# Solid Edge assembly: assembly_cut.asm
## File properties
Author: ptcarter
Template: Normal.asm
Last saved by: ptcarter
Revision: 33
Application: Solid Edge
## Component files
baseplate.psm
motormount.psm
motor.par
M5x10phs.Par
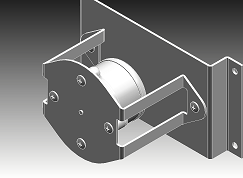
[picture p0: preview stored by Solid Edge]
